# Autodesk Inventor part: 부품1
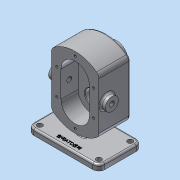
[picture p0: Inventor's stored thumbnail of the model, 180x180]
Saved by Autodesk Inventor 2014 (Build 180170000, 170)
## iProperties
Created: 2019-03
Part Number: 부품1
Material: 알루미늄 6061
Document SubType Name: Modeling
Designer: NET
Density: 2.71 g/cm^3
Appearance: 알루미늄 - 평지
Mass: 1190.84 g
Surface Area: 719.517 cm^2
Volume: 439.424 cm^3
Author: NET
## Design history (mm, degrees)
sketch "스케치1"
  geometry: L1 (-40, -60)-(40, -60); L2 (40, -60)-(40, 60); L3 (40, 60)-(-40, 60); L4 (-40, 60)-(-40, -60); L5 (-40, -60)-(40, 60); L6 (40, -60)-(-40, 60); L7 (0, 0)-(40, 0); L8 (40, 0)-(0, 0); L9 (0, 0)-(40, 0); A1 r 60 centre (0, 0) between (0, 60) and (-40, 44.721); A2 r 60 centre (0, 0) between (40, 44.721) and (0, 60); 3 further points
  constraints: 18 end point, 7 midpoint, 4 point on circle, 3 coincident, 2 centre point, 2 parallel, 2 perpendicular, 2 point on line, 1 concentric, 1 horizontal
  dimensions: "d1" = 80 distance of L2.end L3.end; "d2" = 120 distance of L1.end L2.end; "d4" = 60 radius of A1; "d5" = 60 radius of A2
extrude "돌출1" new body sketch "스케치1" stored distance "d6" = 53; taper "d7" = 0 deg
extrude "돌출2" cut sketch "스케치1" stored distance "d8" = 53; taper "d9" = 0 deg
fillet "모깎기1" dims "d10" = 10
sketch "스케치2"
  geometry: L1 (40, -40)-(40, 40) reference; L2 (0, 22)-(0, -22); L3 (24, 22)-(24, -22); L4 (-24, -22)-(-24, 22); A1 r 24 centre (0, 22) between (24, 22) and (-24, 22); A2 r 24 centre (0, -22) between (-24, -22) and (24, -22); 2 further points
  constraints: 8 end point, 4 point on circle, 4 tangent, 2 centre point, 2 parallel, 1 midpoint, 1 vertical alignment
  dimensions: "d11" = 24 radius of A1; "d12" = 44 distance of L2.end L2.start; "d13" = 22 distance of point (0, 0) L2.start
extrude "돌출3" cut sketch "스케치2" distance "d14" = 29; taper "d15" = 0 deg
sketch "스케치3"
  geometry: C1 r 12.5 at (0, -22); A1 r 24 centre (0, -22) between (-24, -22) and (24, -22) reference; 1 further point
  constraints: 1 centre point, 1 coincident
  dimensions: "d16" = 25 diameter of C1
extrude "돌출4" cut sketch "스케치3" distance "d17" = 15; taper "d18" = 0 deg
sketch "스케치4"
  geometry: C1 r 12.5 at (0, 22); A1 r 24 centre (0, 22) between (24, 22) and (-24, 22) reference; 1 further point
  constraints: 1 centre point, 1 coincident
  dimensions: "d19" = 25 diameter of C1
extrude "돌출5" cut sketch "스케치4" distance "d20" = 15; taper "d21" = 0 deg
sketch "스케치5"
  geometry: C1 r 12.5 at (0, 0) reference; C2 r 8.5 at (0, 0); 1 further point
  constraints: 1 centre point, 1 coincident
  dimensions: "d22" = 17 diameter of C2
extrude "돌출6" cut sketch "스케치5" stored distance "d23" = 15; taper "d24" = 0 deg
sketch "스케치6"
  geometry: C1 r 8.5 at (0, -22) reference; C2 r 19 at (0, -22); 1 further point
  constraints: 1 centre point, 1 coincident
  dimensions: "d25" = 38 diameter of C2
extrude "돌출7" join sketch "스케치6" distance "d26" = 17; taper "d27" = 0 deg
sketch "스케치7"
  geometry: C1 r 8.5 at (0, 0) reference; C2 r 19 at (0, 0) reference; C3 r 14 at (0, 0); 1 further point
  constraints: 1 centre point, 1 coincident
  dimensions: "d28" = 28 diameter of C3
extrude "돌출8" cut sketch "스케치7" distance "d29" = 8; taper "d30" = 0 deg
sketch "스케치8"
  geometry: L1 (2.5, 46)-(-26.5, 46) reference; L2 (-26.5, 46)-(-26.5, 60) reference; L3 (-26.5, 60)-(26.5, 60) reference; L4 (26.5, 60)-(26.5, 41) reference; L5 (26.5, 41)-(43.5, 41) reference; L6 (43.5, 41)-(43.5, 36) reference; L7 (43.5, 36)-(35.5, 36) reference; L8 (35.5, 36)-(35.5, 30.5) reference; L9 (35.5, 30.5)-(17.5, 30.5) reference; L10 (17.5, 30.5)-(17.5, 34.5) reference; L11 (17.5, 34.5)-(2.5, 34.5) reference; L12 (2.5, 34.5)-(2.5, 46) reference; L13 (-26.5, -46)-(2.5, -46) reference; L14 (2.5, -46)-(2.5, -34.5) reference; L15 (2.5, -34.5)-(17.5, -34.5) reference; L16 (17.5, -34.5)-(17.5, -9.5) reference; L17 (17.5, -9.5)-(2.5, -9.5) reference; L18 (2.5, -9.5)-(2.5, 9.5) reference; L19 (2.5, 9.5)-(17.5, 9.5) reference; L20 (17.5, 9.5)-(17.5, 13.5) reference; L21 (17.5, 13.5)-(35.5, 13.5) reference; L22 (35.5, 13.5)-(35.5, 8) reference; L23 (35.5, 8)-(43.5, 8) reference; L24 (43.5, 8)-(43.5, 3) reference; L25 (43.5, 3)-(26.5, 3) reference; L26 (26.5, 3)-(26.5, -60) reference; L27 (26.5, -60)-(-26.5, -60) reference; L28 (-26.5, -60)-(-26.5, -46) reference; L29 (42.8, 36)-(43.5, 36.404); L30 (35.5, 36)-(35.5, 8) reference; L31 (43.5, 36)-(43.5, 8) reference; L32 (17.5, 9.5)-(17.5, 34.5) reference; L33 (2.5, 9.5)-(2.5, 34.5) reference; L34 (43.5, 22)-(2.5, 22); 1 further point
  constraints: 4 end point, 2 midpoint, 2 point on line
  dimensions: "d31" = 0.7 distance of L6.end L29.start; "d32" = 30 deg angle of L7 L29
revolve "회전1" sketch "스케치8" stored, may be unused: angle "d33" = 90 deg
fillet "모깎기2" dims "d34" = 0.5
chamfer "모따기1" distance "d35" = 1; stored, may be unused: second distance "d36" = 2, angle "d37" = 45 deg
node "작업 평면1"
sketch "스케치9"
  geometry: L1 (36, 26.5)-(-36, 26.5) reference; L2 (60, -46.5)-(-60, -46.5); L3 (-60, -46.5)-(-60, 26.5); L4 (-60, 26.5)-(60, 26.5); L5 (60, 26.5)-(60, -46.5); L6 (60, -46.5)-(-60, 26.5); L7 (-60, -46.5)-(60, 26.5); 3 further points
  constraints: 12 end point, 3 midpoint, 2 parallel, 1 horizontal, 1 horizontal alignment, 1 perpendicular, 1 vertical alignment
  dimensions: "d39" = 73 distance of L2.end L3.end; "d40" = 120 distance of L3.end L4.end
extrude "돌출9" join sketch "스케치9" distance "d41" = 10; taper "d42" = 0 deg
sketch "스케치10"
  geometry: 1 further point
sketch "스케치11"
  geometry: L1 (60, 26.5)-(-60, 26.5) reference; L2 (-6, 26.5)-(6, 26.5); L3 (6, 26.5)-(6, -16.5); L4 (6, -16.5)-(-6, -16.5); L5 (-6, -16.5)-(-6, 26.5); 2 further points
  constraints: 8 end point, 2 parallel, 1 horizontal, 1 midpoint, 1 perpendicular, 1 point on line, 1 vertical alignment
  dimensions: "d43" = 12 distance of L3.end L4.end; "d44" = 43 distance of L4.end L2.start
extrude "돌출10" join sketch "스케치11" stored distance "d45" = 10; taper "d46" = 0 deg
fillet "모깎기3" dims "d47" = 10
fillet "모깎기4" dims "d48" = 3
fillet "모깎기5" dims "d49" = 3
fillet "모깎기6" dims "d50" = 3
fillet "모깎기7" dims "d51" = 3
fillet "모깎기8" dims "d52" = 3
sketch "스케치12"
  geometry: L1 (24, 22)-(24, -22) reference; L2 (-24, -22)-(-24, 22) reference; L3 (40, -40)-(40, 40) reference; L4 (-40, 40)-(-40, -40) reference; A1 r 24 centre (0, 22) between (24, 22) and (-24, 22) reference; A2 r 24 centre (0, -22) between (-24, -22) and (24, -22) reference; A3 r 10 centre (-30, -40) between (-40, -40) and (-36, -48) reference; A4 r 60 centre (0, 0) between (-36, -48) and (36, -48) reference; A5 r 10 centre (30, -40) between (36, -48) and (40, -40) reference; A6 r 10 centre (30, 40) between (40, 40) and (36, 48) reference; A7 r 60 centre (0, 0) between (36, 48) and (-36, 48) reference; A8 r 10 centre (-30, 40) between (-36, 48) and (-40, 40) reference
sketch "스케치13"
  geometry: A1 r 24 centre (0, 22) between (24, 22) and (-24, 22) reference; 3 further points
  constraints: 2 horizontal alignment, 1 vertical alignment
  dimensions: "d53" = 62 distance of point (31, 22) point (-31, 22); "d54" = 31 distance of A1.centre point (-31, 22); "d55" = 31 distance of A1.centre point (0, 53)
hole "구멍1" sketch "스케치13" at (31, 22), (0, 53), (-31, 22) diameter "d56" = 4.134; stored, may be unused: countersink angle "d60" = 90 deg, drill point angle "d62" = 118 deg; dims "d57" = 10, "d58" = 4, "d59" = 2, "d61" = 12
sketch "스케치14"
  geometry: L1 (108, -17)-(108, 50) reference; L2 (111, 53)-(118, 53) reference; L3 (118, 53)-(118, -20) reference; L4 (118, -20)-(111, -20) reference; L5 (80, 0)-(0, 0) reference; L6 (0, 53)-(0, 0) reference; L7 (80, 0)-(80, 53) reference; L8 (108, -17)-(108, 50) reference; L9 (111, 53)-(118, 53) reference; L10 (118, 53)-(118, -20) reference; L11 (118, -20)-(111, -20) reference; L12 (80, 0)-(0, 0) reference; L13 (0, 53)-(0, 0) reference; L14 (80, 0)-(80, 53) reference; L15 (-8, 53)-(-8, 0) reference; L16 (-8, 0)-(-8, 53) reference; L17 (-8, 0)-(-8, 0) reference; L18 (-8, 53)-(-8, 0) reference; L19 (95.067, 0)-(90.933, 0) reference; L20 (64.067, 0)-(59.933, 0) reference; L21 (64.067, 0)-(59.933, 0) reference; L22 (-10.933, 0)-(-15.067, 0) reference; L23 (20.067, 0)-(15.933, 0) reference; L24 (20.067, 0)-(15.933, 0) reference; L25 (18, 0)-(18, 0) reference; L26 (18, 0)-(62, 0) reference; L27 (62, 0)-(62, 0) reference; L28 (62, 0)-(18, 0) reference; L29 (88, 0)-(80, 0) reference; L30 (88, 0)-(88, 0) reference; L31 (80, 0)-(88, 0) reference; L32 (80, 0)-(0, 0) reference; L33 (-8, 0)-(0, 0) reference; L34 (-8, 0)-(-8, 0) reference; L35 (0, 0)-(-8, 0) reference; L36 (0, 0)-(80, 0) reference; L37 (0, 53)-(80, 53) reference; L38 (0, 53)-(80, 53) reference; L39 (-8, 53)-(-8, 53) reference; C1 r 11 at (40, 14); A1 r 3 centre (111, -17) between (108, -17) and (111, -20) reference; A2 r 3 centre (111, 50) between (111, 53) and (108, 50) reference; A3 r 3 centre (111, -17) between (108, -17) and (111, -20) reference; A4 r 3 centre (111, 50) between (111, 53) and (108, 50) reference; 2 further points
  constraints: 1 centre point, 1 vertical alignment
  dimensions: "d63" = 22 diameter of C1; "d64" = 14 distance from line of L28 C1.centre
extrude "돌출11" join sketch "스케치14" distance "d65" = 8; taper "d66" = 0 deg
sketch "스케치15"
  geometry: C1 r 11 at (0, 0) reference; 2 further points
  constraints: 1 coincident
hole "구멍2" sketch "스케치15" at (0, 0) diameter "d67" = 8.376; stored, may be unused: countersink angle "d71" = 90 deg, drill point angle "d73" = 118 deg; dims "d68" = 10, "d69" = 4, "d70" = 2, "d72" = 12
fillet "모깎기9" dims "d74" = 3
sketch "스케치16"
  geometry: C1 r 4.5 at (-50, 16.5); C2 r 4.5 at (-50, -36.5); A1 r 7 centre (-50, 16.5) between (-50, 23.5) and (-57, 16.5) reference; A2 r 7 centre (-50, -36.5) between (-57, -36.5) and (-50, -43.5) reference; 1 further point
  constraints: 2 centre point, 2 coincident
  dimensions: "d75" = 9 diameter of C1; "d76" = 9 diameter of C2
extrude "돌출12" cut sketch "스케치16" stored distance "d77" = 8; taper "d78" = 0 deg
fillet "모깎기10" dims "d79" = 3
fillet "모깎기11" dims "d80" = 3
fillet "모깎기12" dims "d81" = 3
fillet "모깎기13" dims "d82" = 3
fillet "모깎기14" dims "d83" = 3
sketch "스케치17"
  geometry: L1 (-50, -46.5)-(50, -46.5) reference; L2 (-60, 16.5)-(-60, -36.5) reference; 2 further points
  constraints: 1 other
  dimensions: "d84" = 10 distance from line of L1 point (0, -36.5); "d85" = 60 distance from line of point (0, -36.5) L2
feature "엠보싱1" sketch "스케치17" dims "d86" = 0.5, "d87" = 0
node "솔리드1"
mirror "대칭1"
mirror "대칭2"
mirror "대칭3"
mirror "대칭4"
node "투영된 루프1"
node "투영된 루프2"
node "투영된 루프3"
node "투영된 루프4"
node "절단 모서리 투영1"
node "절단 모서리 투영2"
node "절단 모서리 투영3"
other parameters: "d38" = -78
